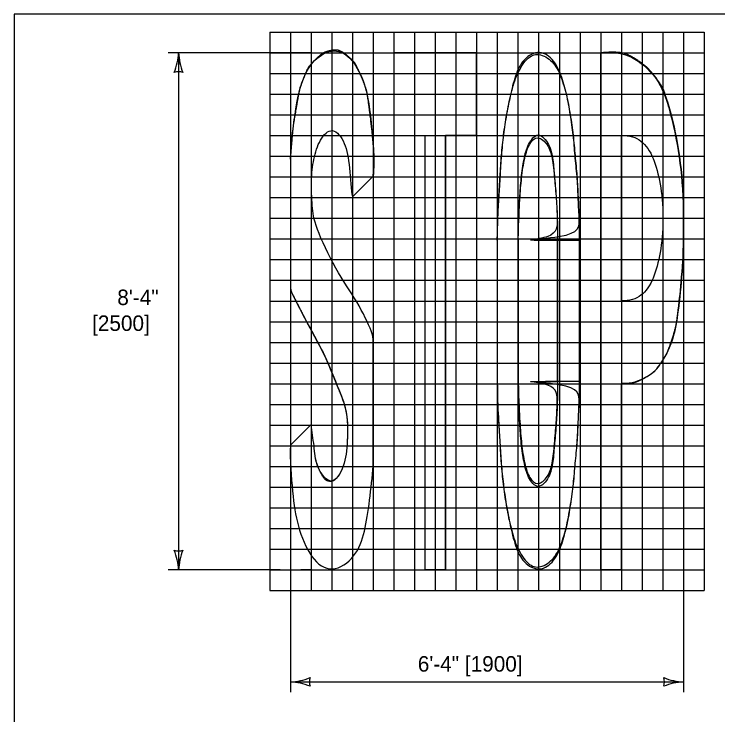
# Model space of a CAD drawing. Extents: x 49991.4 to 50021, y 49987.6 to 50011.4.
# Drawn here: x 50000.336 to 50003.057, y 50008.552 to 50011.263 of the extents above; entities that cross this region are included whole.
import ezdxf

# ---------------------------------------------------------------- set-up
doc = ezdxf.new("R2010")
doc.units = 0
for name, color, linetype in [('Level 1', 7, 'Continuous'), ('Level 2', 7, 'Continuous'), ('Level 3', 7, 'Continuous'), ('Level 9', 7, 'Continuous')]:
    doc.layers.add(name, color=color, linetype=linetype)

msp = doc.modelspace()

# ---------------------------------------------------------------- linework, layer by layer
at = {"layer": 'Level 1'}
for p, q in [((50001.8041, 50011.1131), (50001.8041, 50010.7931)), ((50001.8041, 50011.1131), (50002.1241, 50011.1131)), ((50002.1241, 50011.1131), (50001.8041, 50011.1131)), ((50001.8041, 50011.1131), (50001.8041, 50010.7931)), ((50002.1241, 50011.1131), (50001.8041, 50011.1131)), ((50001.8041, 50011.1131), (50001.8041, 50010.7931)), ((50002.1241, 50011.1131), (50001.8041, 50011.1131)), ((50001.8041, 50011.1131), (50001.8041, 50010.7931)), ((50002.1241, 50011.1131), (50002.1241, 50010.7931)), ((50002.1241, 50010.7931), (50002.1241, 50011.1131)), ((50002.1241, 50010.7931), (50002.1241, 50011.1131)), ((50002.1241, 50010.7931), (50002.1241, 50011.1131)), ((50002.6041, 50009.1136), (50002.6041, 50011.1131)), ((50002.6041, 50011.1131), (50002.6041, 50009.1136)), ((50002.6041, 50011.1131), (50002.6041, 50009.1136)), ((50001.8041, 50010.7931), (50001.9241, 50010.7931)), ((50001.8041, 50010.7931), (50001.9241, 50010.7931)), ((50001.8041, 50010.7931), (50001.9241, 50010.7931)), ((50001.8041, 50010.7931), (50001.9241, 50010.7931)), ((50001.9241, 50010.7931), (50001.9241, 50009.113)), ((50001.9241, 50010.7931), (50001.9241, 50009.113)), ((50001.9241, 50010.7931), (50001.9241, 50009.113)), ((50001.9241, 50010.7931), (50001.9241, 50009.113)), ((50002.1241, 50010.7931), (50002.0041, 50010.7931)), ((50002.0041, 50010.7931), (50002.0041, 50009.113)), ((50002.0041, 50009.113), (50002.0041, 50010.7931)), ((50002.0041, 50010.7931), (50002.1241, 50010.7931)), ((50002.0041, 50009.113), (50002.0041, 50010.7931)), ((50002.0041, 50010.7931), (50002.1241, 50010.7931)), ((50002.0041, 50009.113), (50002.0041, 50010.7931)), ((50002.0041, 50010.7931), (50002.1241, 50010.7931)), ((50002.6841, 50010.1534), (50002.6841, 50010.7932)), ((50002.6841, 50010.1534), (50002.6841, 50010.7932)), ((50002.6841, 50010.1534), (50002.6841, 50010.7932)), ((50001.4039, 50010.7019), (50001.4039, 50010.2119)), ((50001.4039, 50010.7019), (50001.4039, 50010.2119)), ((50001.4039, 50010.7019), (50001.4039, 50010.2119)), ((50001.7239, 50010.6354), (50001.6439, 50010.5554)), ((50001.6439, 50010.5554), (50001.7239, 50010.6354)), ((50001.6439, 50010.5554), (50001.7239, 50010.6354)), ((50002.2041, 50010.3888), (50002.2041, 50009.8421)), ((50002.2851, 50010.3902), (50002.2851, 50009.8407)), ((50002.4371, 50009.8422), (50002.4371, 50010.3886)), ((50002.5225, 50010.388), (50002.5225, 50009.8429)), ((50001.7239, 50009.5153), (50001.7239, 50010.0058)), ((50001.7239, 50009.5153), (50001.7239, 50010.0058)), ((50001.7239, 50009.5153), (50001.7239, 50010.0058)), ((50002.6841, 50009.8334), (50002.6841, 50009.1136)), ((50002.6841, 50009.1136), (50002.6841, 50009.8334)), ((50002.6841, 50009.1136), (50002.6841, 50009.8334)), ((50001.4039, 50009.5953), (50001.4839, 50009.6753)), ((50001.4839, 50009.6753), (50001.4039, 50009.5953)), ((50001.4839, 50009.6753), (50001.4039, 50009.5953)), ((50002.0041, 50009.113), (50001.9241, 50009.113)), ((50001.9241, 50009.113), (50002.0041, 50009.113)), ((50001.9241, 50009.113), (50002.0041, 50009.113)), ((50001.9241, 50009.113), (50002.0041, 50009.113)), ((50002.6841, 50009.1136), (50002.6041, 50009.1136)), ((50002.6041, 50009.1136), (50002.6841, 50009.1136)), ((50002.6041, 50009.1136), (50002.6841, 50009.1136))]:
    msp.add_line(p, q, dxfattribs=at)
msp.add_lwpolyline([(50008.6146, 50011.2628), (50000.3356, 50011.2628), (50000.3356, 50000.0624), (50008.6146, 50000.0624)], close=True, dxfattribs=at)
for points in [[(50002.2041, 50010.3888), (50002.2041, 50009.8421)], [(50002.2851, 50009.8407), (50002.2851, 50010.3902)], [(50002.4371, 50010.3886), (50002.4371, 50009.8422)], [(50002.5225, 50009.8429), (50002.5225, 50010.388)]]:
    msp.add_lwpolyline(points, dxfattribs=at)
for centre, major_axis, start_param, end_param in [((50001.4686, 50010.2119), (0, -0.0677), 4.712389, 5.204685), ((50001.4686, 50010.2119), (0, -0.0677), 4.712389, 5.204685), ((50001.4686, 50010.2119), (0, -0.0677), 4.712389, 5.204685), ((50001.6593, 50010.0058), (0, 0.0677), 4.712389, 5.199618), ((50001.6593, 50010.0058), (0, 0.0677), 4.712404, 5.199618), ((50001.6593, 50010.0058), (0, 0.0677), 4.712389, 5.199618)]:
    msp.add_ellipse(centre, major_axis=major_axis, ratio=0.954505, start_param=start_param, end_param=end_param, dxfattribs=at)
for points, degree in [([(50001.4039, 50010.7019), (50001.4109, 50010.8068), (50001.4314, 50010.9339), (50001.4436, 50010.9917), (50001.4831, 50011.0801), (50001.5637, 50011.1337), (50001.6384, 50011.103), (50001.6896, 50011.0046), (50001.7126, 50010.9068), (50001.7306, 50010.6936), (50001.7239, 50010.6354)], 3), ([(50001.5518, 50011.1195), (50001.5358, 50011.1151), (50001.5198, 50011.1044), (50001.5065, 50011.0922)], 2), ([(50001.5518, 50011.1195), (50001.5358, 50011.1151), (50001.5198, 50011.1044), (50001.5065, 50011.0922)], 2), ([(50001.6281, 50011.0985), (50001.6077, 50011.1156), (50001.5797, 50011.1271), (50001.5518, 50011.1195)], 2), ([(50001.6281, 50011.0985), (50001.6077, 50011.1156), (50001.5797, 50011.1271), (50001.5518, 50011.1195)], 2), ([(50002.5225, 50010.388), (50002.5223, 50010.4146), (50002.5218, 50010.4668), (50002.5166, 50010.546), (50002.5147, 50010.6255), (50002.505, 50010.7053), (50002.5001, 50010.7847), (50002.4881, 50010.8644), (50002.4758, 50010.9448), (50002.454, 50011.019), (50002.4269, 50011.0844), (50002.3687, 50011.1271), (50002.3035, 50011.0916), (50002.2728, 50011.0252), (50002.2537, 50010.9456), (50002.2378, 50010.8658), (50002.2262, 50010.7862), (50002.2188, 50010.706), (50002.214, 50010.6261), (50002.2096, 50010.5458), (50002.2039, 50010.4674), (50002.204, 50010.4146), (50002.2041, 50010.3888)], 3), ([(50002.6041, 50011.1131), (50002.667, 50011.1179), (50002.7371, 50011.0999), (50002.8348, 50011.007), (50002.8791, 50010.8774), (50002.9156, 50010.6887), (50002.925, 50010.5542), (50002.9241, 50010.4733)], 3), ([(50002.7641, 50011.0713), (50002.7198, 50011.1044), (50002.667, 50011.1179), (50002.6041, 50011.1131)], 2), ([(50002.7641, 50011.0713), (50002.7198, 50011.1044), (50002.667, 50011.1179), (50002.6041, 50011.1131)], 2), ([(50001.5065, 50011.0922), (50001.4761, 50011.0642), (50001.4599, 50011.0281), (50001.45, 50011.0017)], 2), ([(50001.5065, 50011.0922), (50001.4761, 50011.0642), (50001.4599, 50011.0281), (50001.45, 50011.0017)], 2), ([(50001.6744, 50011.0299), (50001.6639, 50011.0539), (50001.6506, 50011.0796), (50001.6281, 50011.0985)], 2), ([(50001.6744, 50011.0299), (50001.6639, 50011.0539), (50001.6506, 50011.0796), (50001.6281, 50011.0985)], 2), ([(50002.2041, 50010.3888), (50002.2049, 50010.4663), (50002.2094, 50010.5468), (50002.214, 50010.6243), (50002.2193, 50010.7072), (50002.2269, 50010.7862), (50002.2383, 50010.8645), (50002.2543, 50010.9458), (50002.2755, 50011.0248), (50002.3173, 50011.0947), (50002.3629, 50011.1153), (50002.4207, 50011.0818), (50002.4511, 50011.0233), (50002.4739, 50010.945), (50002.4883, 50010.863), (50002.499, 50010.7847), (50002.5058, 50010.7056), (50002.5134, 50010.6259), (50002.5172, 50010.5445), (50002.521, 50010.4678), (50002.5225, 50010.388), (50002.2041, 50010.3888), (50002.5225, 50010.388)], 3), ([(50002.8041, 50011.0332), (50002.7923, 50011.0475), (50002.7786, 50011.0604), (50002.7641, 50011.0713)], 2), ([(50002.8041, 50011.0332), (50002.7922, 50011.0475), (50002.7786, 50011.0604), (50002.7641, 50011.0713)], 2), ([(50002.9241, 50010.4733), (50002.925, 50010.5542), (50002.9156, 50010.6887), (50002.8791, 50010.8774), (50002.8411, 50010.9885), (50002.8041, 50011.0332)], 3), ([(50002.8761, 50010.8732), (50002.8608, 50010.9308), (50002.8411, 50010.9885), (50002.8041, 50011.0332)], 2), ([(50001.7132, 50010.868), (50001.7039, 50010.9441), (50001.6945, 50010.9839), (50001.6744, 50011.0299)], 2), ([(50001.7132, 50010.8679), (50001.7039, 50010.9441), (50001.6945, 50010.9839), (50001.6744, 50011.0299)], 2), ([(50001.45, 50011.0017), (50001.4401, 50010.9752), (50001.4366, 50010.9586), (50001.4312, 50010.9281)], 2), ([(50001.45, 50011.0017), (50001.4401, 50010.9752), (50001.4366, 50010.9586), (50001.4312, 50010.9281)], 2), ([(50001.4312, 50010.9281), (50001.4232, 50010.8828), (50001.4109, 50010.8068), (50001.4039, 50010.7019)], 2), ([(50001.4312, 50010.9281), (50001.4232, 50010.8828), (50001.4109, 50010.8068), (50001.4039, 50010.7019)], 2), ([(50002.9081, 50010.7132), (50002.9005, 50010.7669), (50002.8902, 50010.82), (50002.8761, 50010.8732)], 2), ([(50001.7239, 50010.6354), (50001.7306, 50010.6936), (50001.7219, 50010.7967), (50001.7132, 50010.8679)], 2), ([(50001.7239, 50010.6354), (50001.7306, 50010.6936), (50001.7219, 50010.7967), (50001.7132, 50010.8679)], 2), ([(50001.7164, 50010.0375), (50001.7059, 50010.0641), (50001.6641, 50010.1518), (50001.5794, 50010.271), (50001.4961, 50010.4484), (50001.4884, 50010.5169), (50001.483, 50010.6197), (50001.493, 50010.7016), (50001.5158, 50010.7793), (50001.5667, 50010.8313), (50001.6184, 50010.7674), (50001.6336, 50010.676), (50001.6394, 50010.5807), (50001.6439, 50010.5554)], 3), ([(50001.7164, 50010.0375), (50001.7059, 50010.0641), (50001.6641, 50010.1518), (50001.5794, 50010.271), (50001.4961, 50010.4484), (50001.4884, 50010.5169), (50001.483, 50010.6197), (50001.493, 50010.7016), (50001.5158, 50010.7793), (50001.5667, 50010.8313), (50001.6184, 50010.7674), (50001.6336, 50010.676), (50001.6394, 50010.5807), (50001.6439, 50010.5554)], 3), ([(50001.7164, 50010.0375), (50001.7059, 50010.0641), (50001.6641, 50010.1518), (50001.5794, 50010.271), (50001.4961, 50010.4484), (50001.4884, 50010.5169), (50001.483, 50010.6197), (50001.493, 50010.7016), (50001.5158, 50010.7793), (50001.5667, 50010.8313), (50001.6184, 50010.7674), (50001.6336, 50010.676), (50001.6394, 50010.5807), (50001.6439, 50010.5554)], 3), ([(50002.2851, 50010.3902), (50002.2857, 50010.4173), (50002.2869, 50010.4705), (50002.291, 50010.5504), (50002.2961, 50010.6296), (50002.3071, 50010.7031), (50002.3206, 50010.7589), (50002.3617, 50010.8128), (50002.4077, 50010.7589), (50002.42, 50010.701), (50002.4254, 50010.6282), (50002.433, 50010.5492), (50002.437, 50010.469), (50002.437, 50010.416), (50002.4371, 50010.3886)], 3), ([(50002.6841, 50010.7932), (50002.7162, 50010.7931), (50002.7639, 50010.7796), (50002.8106, 50010.71), (50002.8352, 50010.6085), (50002.8454, 50010.528), (50002.8441, 50010.4733)], 3), ([(50002.6841, 50010.7932), (50002.7162, 50010.7931), (50002.7639, 50010.7796), (50002.8106, 50010.71), (50002.8352, 50010.6085), (50002.8454, 50010.528), (50002.8441, 50010.4733)], 3), ([(50002.6841, 50010.7932), (50002.7162, 50010.7931), (50002.7639, 50010.7796), (50002.8106, 50010.71), (50002.8352, 50010.6085), (50002.8454, 50010.528), (50002.8441, 50010.4733)], 3), ([(50002.2851, 50010.3902), (50002.2874, 50010.4715), (50002.2912, 50010.5498), (50002.2972, 50010.6295), (50002.3094, 50010.7093), (50002.3276, 50010.7641), (50002.3595, 50010.7952), (50002.4021, 50010.7587), (50002.4173, 50010.7093), (50002.4257, 50010.6288), (50002.4325, 50010.5475), (50002.4363, 50010.4707), (50002.4371, 50010.3886), (50002.2851, 50010.3902), (50002.4371, 50010.3886)], 3), ([(50002.9241, 50010.4733), (50002.925, 50010.5542), (50002.9194, 50010.6343), (50002.9081, 50010.7132)], 2), ([(50002.8441, 50010.4733), (50002.8454, 50010.4185), (50002.8352, 50010.3381), (50002.8106, 50010.2366), (50002.7639, 50010.1669), (50002.7162, 50010.1535), (50002.6841, 50010.1534)], 3), ([(50002.8441, 50010.4733), (50002.8454, 50010.4185), (50002.8352, 50010.3381), (50002.8106, 50010.2366), (50002.7639, 50010.1669), (50002.7162, 50010.1535), (50002.6841, 50010.1534)], 3), ([(50002.8441, 50010.4733), (50002.8454, 50010.4185), (50002.8352, 50010.3381), (50002.8106, 50010.2366), (50002.7639, 50010.1669), (50002.7162, 50010.1535), (50002.6841, 50010.1534)], 3), ([(50002.9241, 50010.4733), (50002.9254, 50010.393), (50002.9218, 50010.2862), (50002.9058, 50010.1259), (50002.889, 50010.0149), (50002.8541, 50009.9376), (50002.8366, 50009.9134), (50002.8366, 50009.9134)], 3), ([(50002.9081, 50010.1534), (50002.9112, 50010.18), (50002.9218, 50010.2862), (50002.9254, 50010.393), (50002.9241, 50010.4733)], 3), ([(50002.9081, 50010.1534), (50002.9112, 50010.18), (50002.9218, 50010.2862), (50002.9254, 50010.393), (50002.9241, 50010.4733)], 3), ([(50001.4116, 50010.1799), (50001.4565, 50010.0929), (50001.4809, 50010.0441), (50001.5387, 50009.9436), (50001.5866, 50009.8195), (50001.6271, 50009.7238), (50001.6254, 50009.6073), (50001.6152, 50009.5132), (50001.5625, 50009.4278), (50001.4992, 50009.5171), (50001.4979, 50009.5916), (50001.487, 50009.6477), (50001.4839, 50009.6753)], 3), ([(50001.4116, 50010.1799), (50001.4565, 50010.0929), (50001.4809, 50010.0441), (50001.5158, 50009.9835), (50001.5329, 50009.9477)], 3), ([(50001.4116, 50010.1799), (50001.4565, 50010.0929), (50001.4681, 50010.0697), (50001.4821, 50010.0438)], 2), ([(50002.8761, 50009.9934), (50002.8936, 50010.0449), (50002.9018, 50010.0992), (50002.9081, 50010.1534)], 2), ([(50002.8761, 50009.9934), (50002.8936, 50010.0449), (50002.9018, 50010.0992), (50002.9081, 50010.1534)], 2), ([(50001.4821, 50010.0438), (50001.4975, 50010.0153), (50001.5387, 50009.9436), (50001.5741, 50009.852), (50001.5904, 50009.8117)], 3), ([(50002.8366, 50009.9134), (50002.8541, 50009.9376), (50002.8665, 50009.9651), (50002.8761, 50009.9934)], 2), ([(50002.8366, 50009.9134), (50002.8541, 50009.9376), (50002.8665, 50009.9651), (50002.8761, 50009.9934)], 2), ([(50001.5329, 50009.9477), (50001.5544, 50009.903), (50001.5866, 50009.8195), (50001.6271, 50009.7238), (50001.6254, 50009.6073), (50001.6152, 50009.5132), (50001.5625, 50009.4278), (50001.4992, 50009.5171), (50001.4979, 50009.5916), (50001.487, 50009.6477), (50001.4839, 50009.6753)], 3), ([(50002.6841, 50009.8334), (50002.7012, 50009.833), (50002.7338, 50009.8366), (50002.7789, 50009.8575), (50002.8157, 50009.8819), (50002.8313, 50009.9039), (50002.8366, 50009.9134)], 3), ([(50002.7517, 50009.8456), (50002.7607, 50009.8493), (50002.7844, 50009.8612), (50002.8157, 50009.8819), (50002.8313, 50009.9039), (50002.8366, 50009.9134)], 3), ([(50002.7782, 50009.8586), (50002.7927, 50009.8667), (50002.8157, 50009.8819), (50002.8313, 50009.9039), (50002.8366, 50009.9134)], 3), ([(50002.2041, 50009.8421), (50002.204, 50009.8163), (50002.2039, 50009.7635), (50002.2096, 50009.6851), (50002.214, 50009.6048), (50002.2188, 50009.5249), (50002.2262, 50009.4447), (50002.2378, 50009.3651), (50002.2537, 50009.2852), (50002.2728, 50009.2057), (50002.3035, 50009.1392), (50002.3687, 50009.1038), (50002.4269, 50009.1465), (50002.454, 50009.2118), (50002.4758, 50009.2861), (50002.4881, 50009.3665), (50002.5001, 50009.4462), (50002.505, 50009.5256), (50002.5147, 50009.6053), (50002.5166, 50009.6848), (50002.5218, 50009.764), (50002.5223, 50009.8163), (50002.5225, 50009.8429)], 3), ([(50002.2041, 50009.8421), (50002.2049, 50009.7646), (50002.2094, 50009.684), (50002.214, 50009.6065), (50002.2193, 50009.5237), (50002.2269, 50009.4447), (50002.2383, 50009.3664), (50002.2543, 50009.2851), (50002.2755, 50009.206), (50002.3173, 50009.1361), (50002.3629, 50009.1156), (50002.4207, 50009.149), (50002.4511, 50009.2076), (50002.4739, 50009.2858), (50002.4883, 50009.3679), (50002.499, 50009.4462), (50002.5058, 50009.5252), (50002.5134, 50009.605), (50002.5172, 50009.6863), (50002.521, 50009.7631), (50002.5225, 50009.8429), (50002.2041, 50009.8421), (50002.5225, 50009.8429)], 3), ([(50002.2851, 50009.8407), (50002.2874, 50009.7594), (50002.2912, 50009.6811), (50002.2972, 50009.6013), (50002.3094, 50009.5215), (50002.3276, 50009.4668), (50002.3595, 50009.4357), (50002.4021, 50009.4721), (50002.4173, 50009.5215), (50002.4257, 50009.6021), (50002.4325, 50009.6834), (50002.4363, 50009.7601), (50002.4371, 50009.8422), (50002.2851, 50009.8407), (50002.4371, 50009.8422)], 3), ([(50002.4371, 50009.8422), (50002.437, 50009.8149), (50002.437, 50009.7619), (50002.433, 50009.6817), (50002.4254, 50009.6027), (50002.42, 50009.5298), (50002.4077, 50009.472), (50002.3617, 50009.418), (50002.3206, 50009.4719), (50002.3071, 50009.5278), (50002.2961, 50009.6013), (50002.291, 50009.6805), (50002.2869, 50009.7604), (50002.2857, 50009.8136), (50002.2851, 50009.8407)], 3), ([(50002.7782, 50009.8586), (50002.7505, 50009.8418), (50002.7195, 50009.8339), (50002.6841, 50009.8334)], 2), ([(50002.6841, 50009.8334), (50002.7086, 50009.8338), (50002.731, 50009.8377), (50002.7517, 50009.8456)], 2), ([(50002.6841, 50009.8334), (50002.7086, 50009.8338), (50002.731, 50009.8377), (50002.7517, 50009.8456)], 2), ([(50002.7517, 50009.8456), (50002.7607, 50009.8493), (50002.7695, 50009.8537), (50002.7782, 50009.8586)], 2), ([(50001.5904, 50009.8117), (50001.6008, 50009.786), (50001.6099, 50009.7645), (50001.6157, 50009.7399)], 2), ([(50001.6157, 50009.7399), (50001.6266, 50009.6932), (50001.6254, 50009.6073), (50001.6152, 50009.5132), (50001.5808, 50009.4575), (50001.5639, 50009.4558)], 3), ([(50001.5112, 50009.5111), (50001.4988, 50009.5405), (50001.4979, 50009.5916), (50001.487, 50009.6477), (50001.4839, 50009.6753)], 3), ([(50001.4039, 50009.5953), (50001.4022, 50009.5389), (50001.4123, 50009.4039), (50001.429, 50009.2847), (50001.4822, 50009.1527), (50001.5641, 50009.0965), (50001.6588, 50009.162), (50001.6927, 50009.2591), (50001.7106, 50009.3797), (50001.7212, 50009.4742), (50001.7239, 50009.5153)], 3), ([(50001.4039, 50009.5953), (50001.4022, 50009.5389), (50001.4123, 50009.4039), (50001.429, 50009.2847), (50001.4822, 50009.1527), (50001.5641, 50009.0965), (50001.6588, 50009.162), (50001.6927, 50009.2591), (50001.7106, 50009.3797), (50001.7212, 50009.4742), (50001.7239, 50009.5153)], 3), ([(50001.4039, 50009.5953), (50001.4022, 50009.5389), (50001.4123, 50009.4039), (50001.429, 50009.2847), (50001.4822, 50009.1527), (50001.5641, 50009.0965), (50001.6588, 50009.162), (50001.6927, 50009.2591), (50001.7106, 50009.3797), (50001.7212, 50009.4742), (50001.7239, 50009.5153)], 3), ([(50001.5639, 50009.4558), (50001.5441, 50009.4538), (50001.5226, 50009.4841), (50001.5112, 50009.5111)], 2)]:
    msp.add_open_spline(points, degree=degree, dxfattribs=at)
at = {"layer": 'Level 3'}
for p, q in [((50001.4844, 50011.1131), (50000.9316, 50011.1131)), ((50000.9716, 50011.1131), (50000.9716, 50009.1131)), ((50002.9241, 50010.0731), (50002.9241, 50008.6397)), ((50001.4041, 50009.3531), (50001.4041, 50008.6397)), ((50001.3641, 50009.1131), (50000.9316, 50009.1131)), ((50001.4841, 50009.1131), (50001.4441, 50009.1131)), ((50001.4041, 50008.6797), (50002.9241, 50008.6797))]:
    msp.add_line(p, q, dxfattribs=at)
for centre, radius, start, end in [((50000.7495, 50011.1223), 0.2223, 337.456, 357.6395), ((50001.2043, 50011.1246), 0.233, 182.8273, 202.0772), ((50000.9716, 50010.9849), 0.0548, 72.1388, 107.8612), ((50000.9716, 50009.2413), 0.0548, 252.1388, 287.8612), ((50000.7389, 50009.1016), 0.233, 2.8273, 22.0772), ((50001.1938, 50009.104), 0.2223, 157.456, 177.6395), ((50001.3949, 50008.9019), 0.2223, 272.3605, 292.544), ((50001.5323, 50008.6797), 0.0548, 162.1388, 197.8612), ((50002.9333, 50008.9019), 0.2223, 247.456, 267.6395), ((50002.7959, 50008.6797), 0.0548, 342.1388, 17.8612), ((50001.3926, 50008.447), 0.233, 67.9228, 87.1727), ((50002.9356, 50008.447), 0.233, 92.8273, 112.0772)]:
    msp.add_arc(centre, radius, start, end, dxfattribs=at)
at = {"layer": 'Level 9'}
for p, q in [((50001.3241, 50011.1931), (50001.3241, 50009.0331)), ((50001.3241, 50011.1931), (50003.0041, 50011.1931)), ((50001.4041, 50011.1931), (50001.4041, 50009.0331)), ((50001.4841, 50011.1931), (50001.4841, 50009.0331)), ((50001.5641, 50011.1931), (50001.5641, 50009.0331)), ((50001.6441, 50011.1931), (50001.6441, 50009.0331)), ((50001.7241, 50011.1931), (50001.7241, 50009.0331)), ((50001.8041, 50011.1931), (50001.8041, 50009.0331)), ((50001.8841, 50011.1931), (50001.8841, 50009.0331)), ((50001.9641, 50011.1931), (50001.9641, 50009.0331)), ((50002.0441, 50011.1931), (50002.0441, 50009.0331)), ((50002.1241, 50011.1931), (50002.1241, 50009.0331)), ((50002.2041, 50011.1931), (50002.2041, 50009.0331)), ((50002.2841, 50011.1931), (50002.2841, 50009.0331)), ((50002.3641, 50011.1931), (50002.3641, 50009.0331)), ((50002.4441, 50011.1931), (50002.4441, 50009.0331)), ((50002.5241, 50011.1931), (50002.5241, 50009.0331)), ((50002.6041, 50011.1931), (50002.6041, 50009.0331)), ((50002.6841, 50011.1931), (50002.6841, 50009.0331)), ((50002.7641, 50011.1931), (50002.7641, 50009.0331)), ((50002.8441, 50011.1931), (50002.8441, 50009.0331)), ((50002.9241, 50011.1931), (50002.9241, 50009.0331)), ((50003.0041, 50011.1931), (50003.0041, 50009.0331)), ((50001.3241, 50011.1131), (50003.0041, 50011.1131)), ((50001.3241, 50011.0331), (50003.0041, 50011.0331)), ((50001.3241, 50010.9531), (50003.0041, 50010.9531)), ((50001.3241, 50010.8731), (50003.0041, 50010.8731)), ((50001.3241, 50010.7931), (50003.0041, 50010.7931)), ((50001.3241, 50010.7131), (50003.0041, 50010.7131)), ((50001.3241, 50010.6331), (50003.0041, 50010.6331)), ((50001.3241, 50010.5531), (50003.0041, 50010.5531)), ((50001.3241, 50010.4731), (50003.0041, 50010.4731)), ((50001.3241, 50010.3931), (50003.0041, 50010.3931)), ((50001.3241, 50010.3131), (50003.0041, 50010.3131)), ((50001.3241, 50010.2331), (50003.0041, 50010.2331)), ((50001.3241, 50010.1531), (50003.0041, 50010.1531)), ((50001.3241, 50010.0731), (50003.0041, 50010.0731)), ((50001.3241, 50009.9931), (50003.0041, 50009.9931)), ((50001.3241, 50009.9131), (50003.0041, 50009.9131)), ((50001.3241, 50009.8331), (50003.0041, 50009.8331)), ((50001.3241, 50009.7531), (50003.0041, 50009.7531)), ((50001.3241, 50009.6731), (50003.0041, 50009.6731)), ((50001.3241, 50009.5931), (50003.0041, 50009.5931)), ((50001.3241, 50009.5131), (50003.0041, 50009.5131)), ((50001.3241, 50009.4331), (50003.0041, 50009.4331)), ((50001.3241, 50009.3531), (50003.0041, 50009.3531)), ((50001.3241, 50009.2731), (50003.0041, 50009.2731)), ((50001.3241, 50009.1931), (50003.0041, 50009.1931)), ((50001.3241, 50009.1131), (50003.0041, 50009.1131)), ((50001.3241, 50009.0331), (50003.0041, 50009.0331))]:
    msp.add_line(p, q, dxfattribs=at)

# ---------------------------------------------------------------- texts
at = {"layer": 'Level 2'}
for s, p in [('8\'-4"', (50000.7347, 50010.1373)), ('[2500]', (50000.6373, 50010.0373)), ('6\'-4" [1900]', (50001.8968, 50008.7197))]:
    msp.add_text(s, height=0.06, dxfattribs=at).set_placement(p)

doc.saveas('drawing.dxf')
